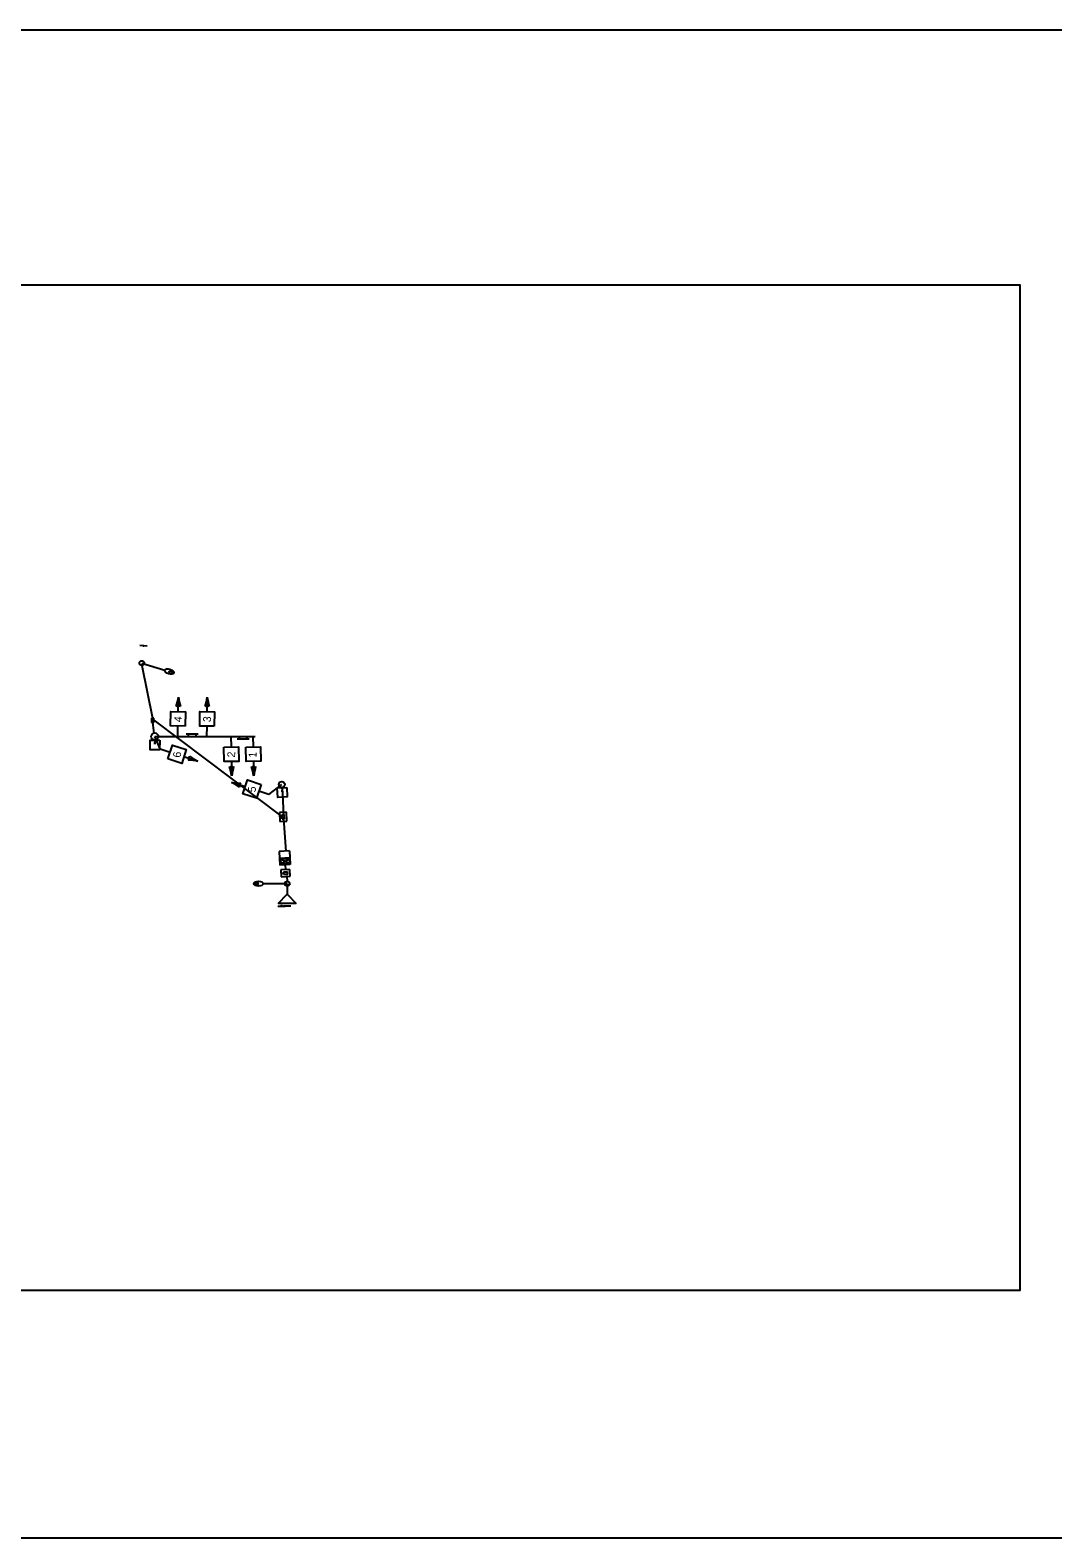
# Model space of a CAD drawing. Extents: x 994065 to 999017, y 1985203 to 1987174.
# Drawn here: x 994728 to 995155, y 1985348 to 1985978 of the extents above; entities that cross this region are included whole.
import ezdxf

# ---------------------------------------------------------------- set-up
doc = ezdxf.new("R2010")
doc.units = 0
for name, color, linetype in [('DSN_Drain_Alignment_ArDOT_BMCD_Rt', 7, 'Continuous'), ('DSN_DRAIN_Analytics_ArDOT_BMCD_Rt', 7, 'Continuous'), ('DSN_DRAIN_Storm-Sewer', 7, 'Continuous'), ('DSN_DRAIN_Storm-Sewer_ArDOT_BMCD_Lt', 7, 'Continuous'), ('EX_CONTOUR_ANNOT_MAJOR', 7, 'Continuous'), ('EX_CONTOUR_ANNOT_MINOR', 7, 'Continuous'), ('EX_TERRAIN', 7, 'Continuous'), ('EX_TERRAIN_BOUNDARY', 7, 'Continuous'), ('Level 23', 7, 'Continuous')]:
    doc.layers.add(name, color=color, linetype=linetype)

msp = doc.modelspace()

# ---------------------------------------------------------------- linework, layer by layer
at = {"layer": 'DSN_Drain_Alignment_ArDOT_BMCD_Rt'}
for p, q in [((994831.41, 1985613.35), (994835.16, 1985617.35)), ((994835.16, 1985621.7), (994835.16, 1985617.35)), ((994835.16, 1985617.35), (994838.91, 1985613.35)), ((994838.91, 1985613.35), (994831.41, 1985613.35))]:
    msp.add_line(p, q, dxfattribs=at)
at = {"layer": 'DSN_DRAIN_Analytics_ArDOT_BMCD_Rt'}
for points in [[(994781.82, 1985681.66), (994781.79, 1985677.66), (994777.79, 1985677.69), (994777.83, 1985681.69)], [(994834.93, 1985661.96), (994835.18, 1985657.97), (994831.18, 1985657.73), (994830.94, 1985661.72)]]:
    msp.add_lwpolyline(points, close=True, dxfattribs=at)
at = {"layer": 'DSN_DRAIN_Storm-Sewer'}
for p, q in [((994774.37, 1985712.88), (994778.88, 1985690.85)), ((994778.88, 1985689.1), (994779.4, 1985684.62)), ((994779.34, 1985689.97), (994832.98, 1985649.61)), ((994833.06, 1985661.85), (994833.54, 1985650.51)), ((994833.63, 1985648.76), (994834.5, 1985635.35)), ((994834.25, 1985629.58), (994834.35, 1985627.59)), ((994835.01, 1985624.7), (994835.11, 1985622.7))]:
    msp.add_line(p, q, dxfattribs=at)
at = {"layer": 'DSN_DRAIN_Storm-Sewer_ArDOT_BMCD_Lt'}
for p, q in [((994797.87, 1985684.18), (994792.87, 1985684.18)), ((994793.87, 1985683.18), (994793.87, 1985684.18)), ((994796.87, 1985684.18), (994796.87, 1985683.18)), ((994797.87, 1985684.18), (994796.87, 1985684.18)), ((994814.22, 1985682.18), (994815.22, 1985682.18)), ((994814.22, 1985682.18), (994819.22, 1985682.18)), ((994815.22, 1985682.18), (994815.22, 1985683.18)), ((994818.22, 1985683.18), (994818.22, 1985682.18))]:
    msp.add_line(p, q, dxfattribs=at)
at = {"layer": 'EX_CONTOUR_ANNOT_MAJOR'}
for p, q in [((994773.54, 1985721.38), (994776.53, 1985721.14)), ((994779.34, 1985690.85), (994778.42, 1985690.85)), ((994778.42, 1985690.85), (994778.42, 1985689.1)), ((994778.42, 1985689.1), (994779.34, 1985689.1)), ((994779.34, 1985689.1), (994779.34, 1985690.85)), ((994779.38, 1985680.36), (994780.25, 1985680.35)), ((994779.83, 1985681.67), (994779.81, 1985680.35)), ((994832.94, 1985661.84), (994833.02, 1985660.53)), ((994832.58, 1985660.5), (994833.45, 1985660.55)), ((994834.8, 1985651.57), (994831.88, 1985651.43)), ((994831.88, 1985651.43), (994832.07, 1985647.68)), ((994833.85, 1985650.53), (994832.93, 1985650.48)), ((994833.85, 1985650.53), (994832.93, 1985650.48)), ((994833.02, 1985648.73), (994832.93, 1985650.48)), ((994832.93, 1985650.48), (994833.02, 1985648.73)), ((994833.94, 1985648.78), (994833.02, 1985648.73)), ((994833.02, 1985648.73), (994833.94, 1985648.78)), ((994833.94, 1985648.78), (994833.85, 1985650.53)), ((994833.94, 1985648.78), (994833.85, 1985650.53)), ((994834.99, 1985647.83), (994834.8, 1985651.57)), ((994832.07, 1985647.68), (994834.99, 1985647.83)), ((994836.23, 1985627.69), (994832.48, 1985627.48)), ((994832.48, 1985627.48), (994832.65, 1985624.56)), ((994832.65, 1985624.56), (994836.39, 1985624.78)), ((994833.54, 1985626.54), (994835.28, 1985626.64)), ((994835.28, 1985626.64), (994833.54, 1985626.54)), ((994833.59, 1985625.62), (994833.54, 1985626.54)), ((994833.54, 1985626.54), (994833.59, 1985625.62)), ((994833.59, 1985625.62), (994835.34, 1985625.72)), ((994833.59, 1985625.62), (994835.34, 1985625.72)), ((994835.34, 1985625.72), (994835.28, 1985626.64)), ((994835.34, 1985625.72), (994835.28, 1985626.64)), ((994836.39, 1985624.78), (994836.23, 1985627.69)), ((994831.23, 1985612.35), (994834.23, 1985612.35))]:
    msp.add_line(p, q, dxfattribs=at)
for centre in [(994775.03, 1985721.13), (994832.73, 1985612.47)]:
    msp.add_circle(centre, 0.125, dxfattribs=at)
at = {"layer": 'EX_CONTOUR_ANNOT_MINOR'}
for p, q in [((994774.37, 1985713.88), (994783.92, 1985710.92)), ((994789.56, 1985693.59), (994789.7, 1985699.63)), ((994801.66, 1985693.59), (994801.71, 1985699.63)), ((994789.36, 1985683.18), (994789.45, 1985687.53)), ((994801.59, 1985683.18), (994801.63, 1985687.53)), ((994782.09, 1985678.09), (994779.76, 1985683.18)), ((994811.62, 1985683.18), (994811.69, 1985678.83)), ((994820.8, 1985683.18), (994820.88, 1985678.83)), ((994782.09, 1985678.09), (994786.22, 1985676.72)), ((994791.98, 1985674.83), (994797.71, 1985672.93)), ((994811.82, 1985672.77), (994811.93, 1985666.73)), ((994821.01, 1985672.77), (994821.12, 1985666.73)), ((994817.53, 1985662.16), (994811.79, 1985664.04)), ((994827.44, 1985658.96), (994832.86, 1985663.09)), ((994827.44, 1985658.96), (994823.3, 1985660.31)), ((994835.16, 1985621.7), (994825.16, 1985621.7))]:
    msp.add_line(p, q, dxfattribs=at)
for points in [[(994792.47, 1985687.46), (994786.41, 1985687.59), (994786.54, 1985693.65), (994792.6, 1985693.52)], [(994804.64, 1985687.5), (994798.58, 1985687.55), (994798.63, 1985693.62), (994804.7, 1985693.56)], [(994785.27, 1985673.86), (994787.18, 1985679.62), (994792.93, 1985677.7), (994791.02, 1985671.95)], [(994808.68, 1985678.78), (994814.74, 1985678.89), (994814.85, 1985672.82), (994808.78, 1985672.72)], [(994817.86, 1985678.78), (994823.93, 1985678.89), (994824.04, 1985672.83), (994817.97, 1985672.72)], [(994824.24, 1985663.18), (994822.36, 1985657.41), (994816.59, 1985659.29), (994818.47, 1985665.05)]]:
    msp.add_lwpolyline(points, close=True, dxfattribs=at)
for centre, radius, start, end in [((994760.66, 1985704.68), 29.47, 342.38565, 350.12376), ((994818.93, 1985703.39), 29.47, 187.3404, 195.07851), ((994772.61, 1985704.29), 29.47, 343.15607, 350.89418), ((994830.89, 1985703.79), 29.47, 188.11082, 195.84893), ((994789.58, 1985694.36), 1.63, 56.88476, 120.5794), ((994801.66, 1985694.36), 1.63, 57.65518, 121.34982), ((994792.71, 1985674.59), 1.63, 309.77139, 13.46603), ((994792.71, 1985643.88), 29.47, 80.22703, 87.96514), ((994811.09, 1985699.19), 29.47, 235.27228, 243.01039), ((994811.83, 1985672), 1.63, 239.15739, 302.85203), ((994782.87, 1985661.81), 29.47, 9.61303, 17.35114), ((994841.14, 1985662.83), 29.47, 164.65828, 172.39639), ((994821.03, 1985672), 1.63, 239.18681, 302.88144), ((994792.07, 1985661.8), 29.47, 9.64244, 17.38055), ((994850.34, 1985662.85), 29.47, 164.68769, 172.42581), ((994816.63, 1985693.11), 29.47, 260.54799, 268.28611), ((994798.56, 1985637.7), 29.47, 55.59325, 63.33136), ((994816.8, 1985662.4), 1.63, 130.09236, 193.787)]:
    msp.add_arc(centre, radius, start, end, dxfattribs=at)
for centre, major_axis in [((994785.83, 1985710.33), (1.91, -0.59)), ((994786.78, 1985710.03), (-0.955, 0.296)), ((994823.16, 1985621.7), (-2, 0)), ((994822.16, 1985621.7), (1, 0))]:
    msp.add_ellipse(centre, major_axis=major_axis, ratio=0.5, dxfattribs=at)
at = {"layer": 'EX_TERRAIN'}
for p, q in [((994836.08, 1985635.44), (994831.76, 1985635.19)), ((994831.76, 1985635.19), (994832.09, 1985629.46)), ((994836.26, 1985632.44), (994831.93, 1985632.2)), ((994836.41, 1985629.71), (994832.09, 1985629.46)), ((994835.95, 1985632.09), (994832.28, 1985631.88)), ((994836.04, 1985630.02), (994832.28, 1985631.88)), ((994832.28, 1985631.88), (994832.4, 1985629.81)), ((994832.4, 1985629.81), (994835.95, 1985632.09)), ((994836.06, 1985630.02), (994832.4, 1985629.81)), ((994835.95, 1985632.09), (994836.06, 1985630.02)), ((994836.08, 1985635.44), (994836.41, 1985629.71))]:
    msp.add_line(p, q, dxfattribs=at)
at = {"layer": 'EX_TERRAIN_BOUNDARY'}
msp.add_line((994779.76, 1985683.18), (994821.76, 1985683.18), dxfattribs=at)
for centre, radius in [((994774.37, 1985713.88), 1), ((994779.76, 1985683.18), 1.5), ((994832.86, 1985663.09), 1.25), ((994835.16, 1985621.7), 1)]:
    msp.add_circle(centre, radius, dxfattribs=at)
at = {"layer": 'Level 23'}
msp.add_line((994836.63, 1985612.37), (994833.63, 1985612.37), dxfattribs=at)
for points in [[(994300.17, 1985348.35), (995290.18, 1985348.35), (995290.18, 1985978.35), (994300.17, 1985978.35)], [(994481.47, 1985451.79), (995141.47, 1985451.79), (995141.47, 1985871.79), (994481.47, 1985871.79)]]:
    msp.add_lwpolyline(points, close=True, dxfattribs=at)

# ---------------------------------------------------------------- texts
at = {"layer": 'EX_CONTOUR_ANNOT_MINOR'}
for s, rotation, p in [('4', 86.24316, (994791.04, 1985689.11)), ('3', 86.24316, (994803.17, 1985689.13)), ('6', 86.39909, (994790.64, 1985674.34)), ('2', 86.24316, (994813.29, 1985674.35)), ('1', 86.24316, (994822.23, 1985674.24)), ('5', 86.39909, (994821.95, 1985659.8))]:
    msp.add_text(s, height=3.25, rotation=rotation, dxfattribs=at).set_placement(p)

doc.saveas('drawing.dxf')
